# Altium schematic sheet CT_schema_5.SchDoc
size 445 x 328 mm
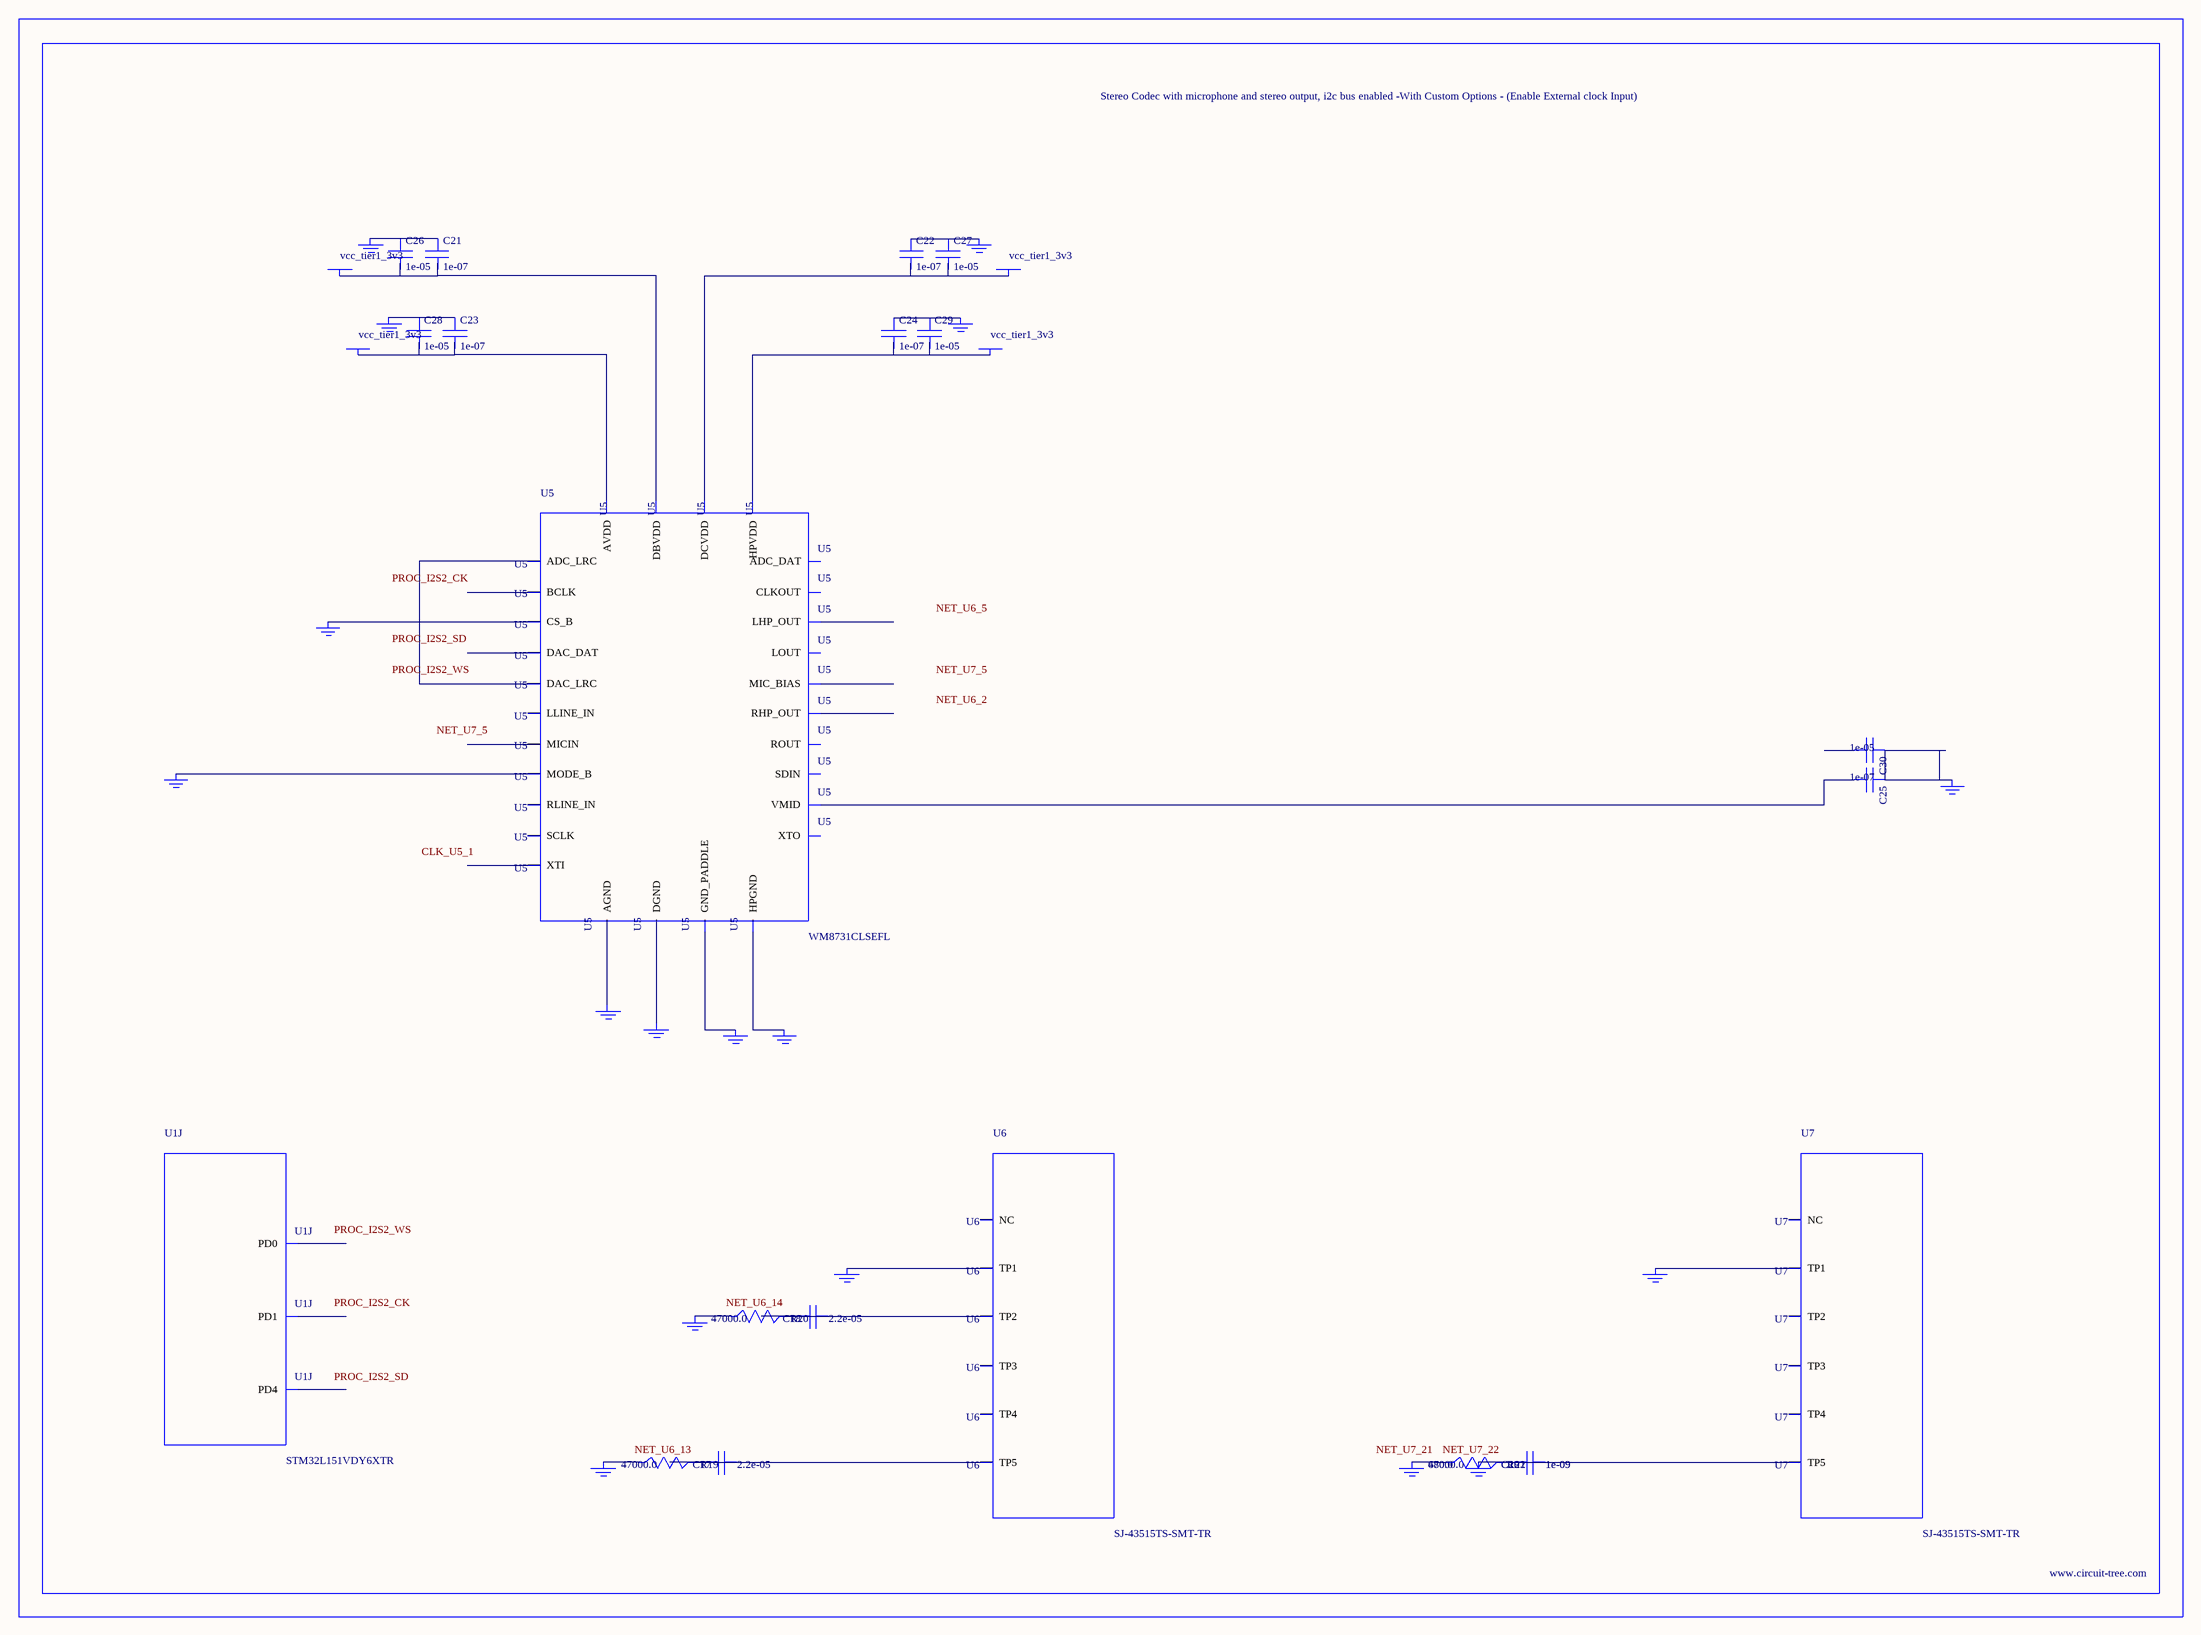
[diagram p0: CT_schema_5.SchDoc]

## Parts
BORDER4  (no value)
C17  2.2e-05  [C1210]
C18  2.2e-05  [C1210]
C19  1e-09  [C0402]
C20  1e-09  [C0402]
C21  1e-07  [C0402]
C22  1e-07  [C0402]
C23  1e-07  [C0402]
C24  1e-07  [C0402]
C25  1e-07  [C0402]
C26  1e-05  [C0805]
C27  1e-05  [C0805]
C28  1e-05  [C0805]
C29  1e-05  [C0805]
C30  1e-05  [C0805]
GND_INSTANCE_4_0  (no value)
GND_INSTANCE_4_1  (no value)
GND_INSTANCE_4_2  (no value)
GND_INSTANCE_4_3  (no value)
GND_INSTANCE_4_4  (no value)
GND_INSTANCE_4_5  (no value)
GND_INSTANCE_4_6  (no value)
GND_INSTANCE_4_7  (no value)
GND_INSTANCE_4_8  (no value)
GND_INSTANCE_4_9  (no value)
GND_INSTANCE_4_10  (no value)
GND_INSTANCE_4_11  (no value)
GND_INSTANCE_4_12  (no value)
GND_INSTANCE_4_13  (no value)
GND_INSTANCE_4_14  (no value)
GND_INSTANCE_4_15  (no value)
GND_INSTANCE_4_16  (no value)
POWER_INSTANCE_4_0  vcc_tier1_3v3
POWER_INSTANCE_4_1  vcc_tier1_3v3
POWER_INSTANCE_4_2  vcc_tier1_3v3
POWER_INSTANCE_4_3  vcc_tier1_3v3
R19  47000.0  [R0603]
R20  47000.0  [R0603]
R21  47000.0  [R0603]
R22  680.0  [R0603]
U1  STM32L151VDY6XTR  [WLCSP104]  (part J of 10)
U5  WM8731CLSEFL  [QFN-28]
U6  SJ-43515TS-SMT-TR  [SJ-43515TS-SMT-TR]
U7  SJ-43515TS-SMT-TR  [SJ-43515TS-SMT-TR]

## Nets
NetC17_1: C17.1 C17.2 R19.2 U6.5(TP5)
NetC18_1: C18.1 C18.2 R20.2 U6.2(TP2)
NetC19_1: C19.1 C19.2 C20.1 C20.2 GND_INSTANCE_4_16.0(GND) R21.2 R22.2 U7.5(TP5)
NetC21_1: C21.1 C26.1 GND_INSTANCE_4_1.0(GND)
NetC21_2: C21.2 C26.2 POWER_INSTANCE_4_1.0(PWR) U5.5(DBVDD)
NetC22_1: C22.1 C27.1 GND_INSTANCE_4_0.0(GND)
NetC22_2: C22.2 C27.2 POWER_INSTANCE_4_0.0(PWR) U5.3(DCVDD)
NetC23_1: C23.1 C28.1 GND_INSTANCE_4_4.0(GND)
NetC23_2: C23.2 C28.2 POWER_INSTANCE_4_3.0(PWR) U5.18(AVDD)
NetC24_1: C24.1 C29.1 GND_INSTANCE_4_2.0(GND)
NetC24_2: C24.2 C29.2 POWER_INSTANCE_4_2.0(PWR) U5.12(HPVDD)
NetC25_1: C25.1 C30.1 GND_INSTANCE_4_5.0(GND)
NetC25_2: C25.2 U5.20(VMID)
NetGND_INSTANCE_4_3_0: GND_INSTANCE_4_3.0(GND) U5.15(HPGND)
NetGND_INSTANCE_4_6_0: GND_INSTANCE_4_6.0(GND) U5.25(MODE_B)
NetGND_INSTANCE_4_7_0: GND_INSTANCE_4_7.0(GND) U5.26(CS_B)
NetGND_INSTANCE_4_8_0: GND_INSTANCE_4_8.0(GND) U5.29(GND_PADDLE)
NetGND_INSTANCE_4_9_0: GND_INSTANCE_4_9.0(GND) U5.4(DGND)
NetGND_INSTANCE_4_10_0: GND_INSTANCE_4_10.0(GND) U5.19(AGND)
NetGND_INSTANCE_4_11_0: GND_INSTANCE_4_11.0(GND) U6.1(TP1)
NetGND_INSTANCE_4_12_0: GND_INSTANCE_4_12.0(GND) R20.1
NetGND_INSTANCE_4_13_0: GND_INSTANCE_4_13.0(GND) R19.1
NetGND_INSTANCE_4_14_0: GND_INSTANCE_4_14.0(GND) U7.1(TP1)
NetGND_INSTANCE_4_15_0: GND_INSTANCE_4_15.0(GND) R21.1 R22.1
NetU5_9: U5.9(DAC_LRC) U5.11(ADC_LRC)

Not connected (* = marked no-connect by the designer): C30 2; U1 A2(PD0) A3(PD4) D4(PD1); U5 1(XTI) 2(XTO) 6(CLKOUT) 7(BCLK) 8(DAC_DAT) 10(ADC_DAT) 13(LHP_OUT) 14(RHP_OUT) 16(LOUT) 17(ROUT) 21(MIC_BIAS) 22(MICIN) 23(RLINE_IN) 24(LLINE_IN) 27(SDIN) 28(SCLK); U6 3(TP3) 4(TP4) 6(NC); U7 2(TP2) 3(TP3) 4(TP4) 6(NC)

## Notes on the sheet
- Labels drawn without touching a wire or pin: CLK_U5_1, NET_U6_2, NET_U6_5, NET_U6_13, NET_U6_14, NET_U7_5, NET_U7_21, NET_U7_22, PROC_I2S2_CK, PROC_I2S2_SD, PROC_I2S2_WS

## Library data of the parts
BORDER4 = BORDER_PAGE4
C17 C18 = C1210C224K5RACTU
C19 C20 = C0402C102K3RAC
C21-C25 = C0402C104K3RACTU
C26-C30 = C0805C106K8RACTU
GND_INSTANCE_4_0-GND_INSTANCE_4_16 = GND
POWER_INSTANCE_4_0-POWER_INSTANCE_4_3 = PWR
R19-R21 = RC0603JR-0747KL
R22 = RC0603JR-07680RL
